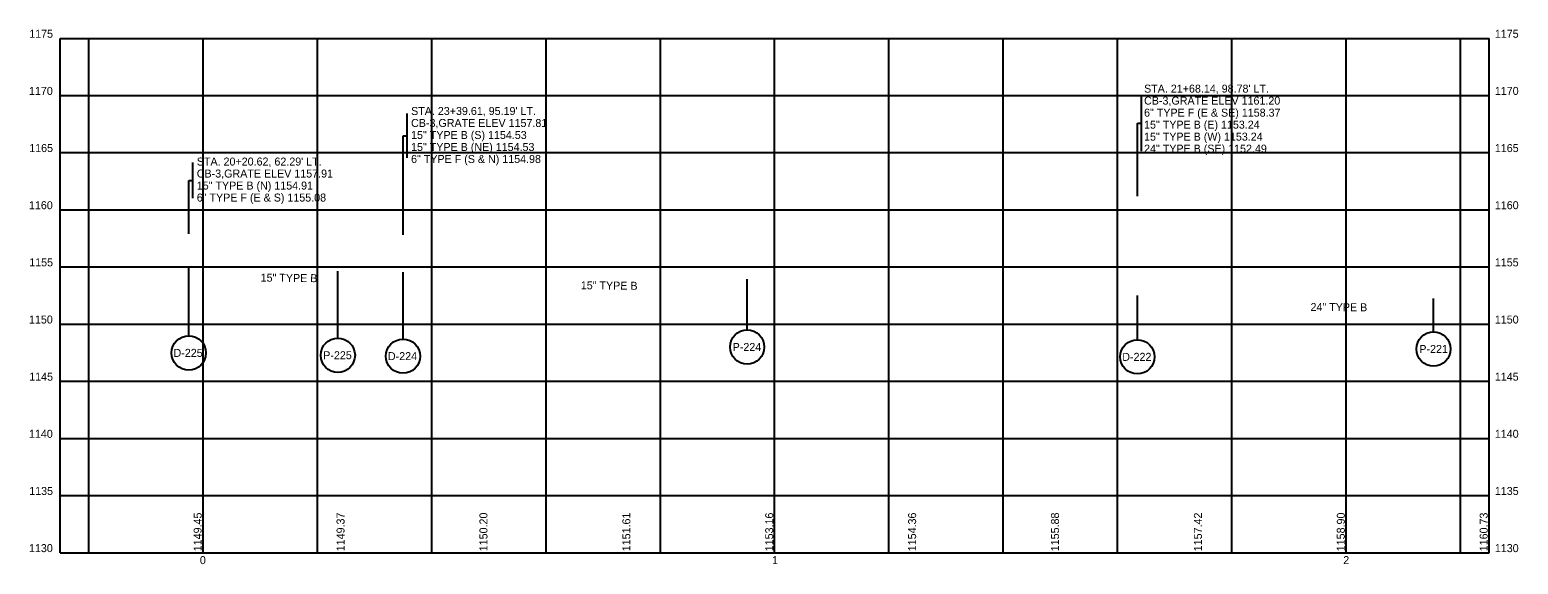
# Model space of a CAD drawing. Extents: x -30 to 230, y 1128 to 1222.
import ezdxf

# ---------------------------------------------------------------- set-up
doc = ezdxf.new("R2010")
doc.units = 0
for name, color, linetype in [('DR_P_Text', 7, 'Continuous'), ('PF_P_Sta_Elev_Text', 7, 'Continuous'), ('PF_X_Text_Strip_Grade', 7, 'Continuous'), ('SH_Major_Grid_Line', 7, 'Continuous')]:
    doc.layers.add(name, color=color, linetype=linetype)

msp = doc.modelspace()

# ---------------------------------------------------------------- linework, layer by layer
at = {"layer": 'DR_P_Text'}
for p, q in [((164.17, 1200.26), (164.17, 1209.99)), ((35.69, 1199.09), (35.69, 1206.85)), ((163.47, 1205.13), (164.17, 1205.13)), ((163.47, 1192.4), (163.47, 1205.13)), ((34.99, 1202.96), (35.69, 1202.96)), ((34.99, 1185.62), (34.99, 1202.96)), ((-1.8, 1192.05), (-1.8, 1198.25)), ((-2.5, 1195.15), (-1.8, 1195.15)), ((-2.5, 1185.82), (-2.5, 1195.15))]:
    msp.add_line(p, q, dxfattribs=at)
at = {"layer": 'PF_P_Sta_Elev_Text'}
for p, q in [((-2.5, 1167.96), (-2.5, 1179.82)), ((23.58, 1167.55), (23.58, 1179.28)), ((34.99, 1167.39), (34.99, 1179.06)), ((95.19, 1168.99), (95.19, 1177.85)), ((163.47, 1167.27), (163.47, 1174.98)), ((215.27, 1168.64), (215.27, 1174.46))]:
    msp.add_line(p, q, dxfattribs=at)
for centre in [(-2.5, 1164.96), (23.58, 1164.55), (34.99, 1164.39), (95.19, 1165.99), (163.47, 1164.27), (215.27, 1165.64)]:
    msp.add_circle(centre, 3, dxfattribs=at)
at = {"layer": 'SH_Major_Grid_Line'}
for p, q in [((-25, 1220), (225, 1220)), ((-25, 1130), (-25, 1220)), ((-20, 1130), (-20, 1220)), ((0, 1130), (0, 1220)), ((20, 1130), (20, 1220)), ((40, 1130), (40, 1220)), ((60, 1130), (60, 1220)), ((80, 1130), (80, 1220)), ((100, 1130), (100, 1220)), ((120, 1130), (120, 1220)), ((140, 1130), (140, 1220)), ((160, 1130), (160, 1220)), ((180, 1130), (180, 1220)), ((200, 1130), (200, 1220)), ((220, 1130), (220, 1220)), ((225, 1130), (225, 1220)), ((-25, 1210), (225, 1210)), ((-25, 1200), (225, 1200)), ((-25, 1190), (225, 1190)), ((-25, 1180), (225, 1180)), ((-25, 1170), (225, 1170)), ((-25, 1160), (225, 1160)), ((-25, 1150), (225, 1150)), ((-25, 1140), (225, 1140)), ((-25, 1130), (225, 1130))]:
    msp.add_line(p, q, dxfattribs=at)

# ---------------------------------------------------------------- texts
at = {"layer": 'DR_P_Text'}
for s, p in [("STA. 21+68.14, 98.78' LT.", (164.63, 1210.5)), ('CB-3,GRATE ELEV 1161.20', (164.63, 1208.4)), ("STA. 23+39.61, 95.19' LT.", (36.39, 1206.59)), ('CB-3,GRATE ELEV 1157.81', (36.39, 1204.49)), ('6" TYPE F (E & SE) 1158.37', (164.63, 1206.3)), ('15" TYPE B (S) 1154.53', (36.39, 1202.39)), ('15" TYPE B (E) 1153.24 ', (164.63, 1204.2)), ('15" TYPE B (W) 1153.24', (164.63, 1202.1)), ('15" TYPE B (NE) 1154.53', (36.39, 1200.29)), ('24" TYPE B (SE) 1152.49 ', (164.63, 1200)), ("STA. 20+20.62, 62.29' LT.", (-1.1, 1197.74)), ('6" TYPE F (S & N) 1154.98', (36.39, 1198.19)), ('CB-3,GRATE ELEV 1157.91', (-1.1, 1195.64)), ('6" TYPE F (E & S) 1155.08', (-1.1, 1191.44)), ('15" TYPE B (N) 1154.91', (-1.1, 1193.54))]:
    msp.add_text(s, height=1.4, dxfattribs=at).set_placement(p)
at = {"layer": 'PF_P_Sta_Elev_Text'}
for s, p in [('1175', (-30.42, 1220.1)), ('1175', (226, 1220.1)), ('1170', (-30.46, 1210.1)), ('1170', (226, 1210.1)), ('1165', (-30.42, 1200.1)), ('1165', (226, 1200.1)), ('1160', (-30.46, 1190.1)), ('1160', (226, 1190.1)), ('1155', (-30.42, 1180.1)), ('1155', (226, 1180.1)), ('1150', (-30.46, 1170.1)), ('1150', (226, 1170.1)), ('P-224', (92.65, 1165.29)), ('D-225', (-5.17, 1164.26)), ('P-225', (21.02, 1163.85)), ('D-224', (32.34, 1163.69)), ('D-222', (160.82, 1163.57)), ('P-221', (212.79, 1164.94)), ('1145', (-30.42, 1160.1)), ('1145', (226, 1160.1)), ('1140', (-30.46, 1150.1)), ('1140', (226, 1150.1)), ('1135', (-30.42, 1140.1)), ('1135', (226, 1140.1)), ('1130', (-30.46, 1130.1)), ('1130', (226, 1130.1)), ('0', (-0.56, 1128)), ('1', (99.54, 1128)), ('2', (199.48, 1128))]:
    msp.add_text(s, height=1.4, dxfattribs=at).set_placement(p)
for s, rotation, p in [('15" TYPE B', 359.3451, (10.07, 1177.44)), ('15" TYPE B', 359.4086, (66.08, 1176.1)), ('24" TYPE B', 359.7046, (193.75, 1172.29))]:
    msp.add_text(s, height=1.4, rotation=rotation, dxfattribs=at).set_placement(p)
at = {"layer": 'PF_X_Text_Strip_Grade'}
for s, p in [('1149.45', (-0.25, 1130.25)), ('1149.45', (-0.25, 1130.25)), ('1149.45', (-0.25, 1130.25)), ('1149.37', (24.75, 1130.25)), ('1149.37', (24.75, 1130.25)), ('1149.37', (24.75, 1130.25)), ('1150.20', (49.75, 1130.25)), ('1150.20', (49.75, 1130.25)), ('1150.20', (49.75, 1130.25)), ('1151.61', (74.75, 1130.25)), ('1151.61', (74.75, 1130.25)), ('1151.61', (74.75, 1130.25)), ('1153.16', (99.75, 1130.25)), ('1153.16', (99.75, 1130.25)), ('1153.16', (99.75, 1130.25)), ('1154.36', (124.75, 1130.25)), ('1154.36', (124.75, 1130.25)), ('1154.36', (124.75, 1130.25)), ('1155.88', (149.75, 1130.25)), ('1155.88', (149.75, 1130.25)), ('1155.88', (149.75, 1130.25)), ('1157.42', (174.75, 1130.25)), ('1157.42', (174.75, 1130.25)), ('1157.42', (174.75, 1130.25)), ('1158.90', (199.75, 1130.25)), ('1158.90', (199.75, 1130.25)), ('1158.90', (199.75, 1130.25)), ('1160.73', (224.75, 1130.25)), ('1160.73', (224.75, 1130.25)), ('1160.73', (224.75, 1130.25))]:
    msp.add_text(s, height=1.4, rotation=90, dxfattribs=at).set_placement(p)

doc.saveas('drawing.dxf')
